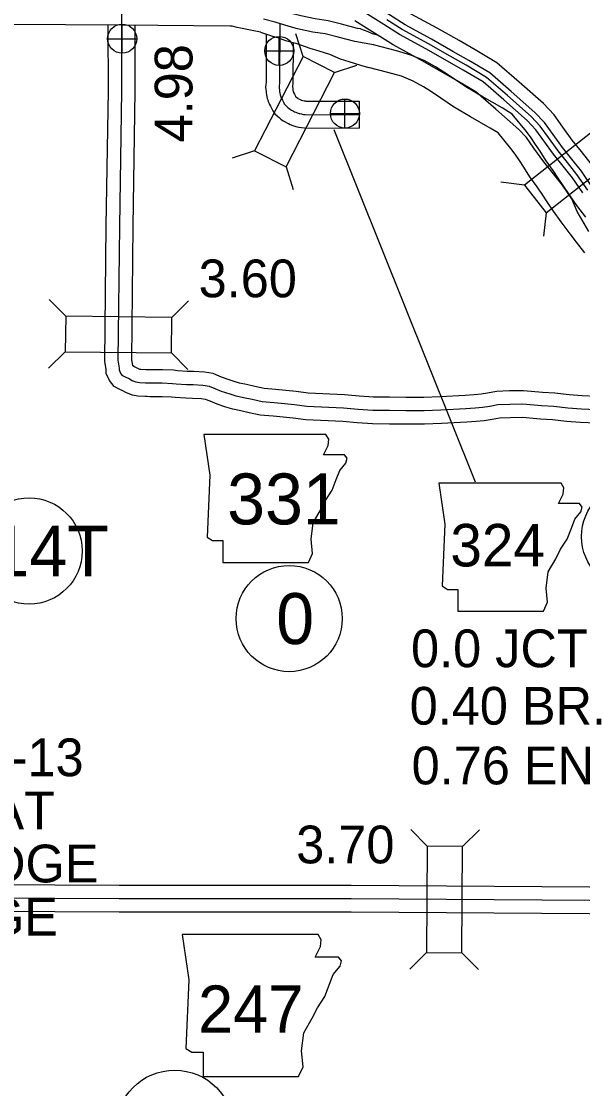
# Model space of a CAD drawing. Extents: x -83719 to 153526, y -11835 to 11446.
# Drawn here: x -1845 to -1635.6, y 787.2 to 1185.3 of the extents above; entities that cross this region are included whole.
import ezdxf

# ---------------------------------------------------------------- set-up
doc = ezdxf.new("R2010")
doc.units = 0
for name, color, linetype in [('Level 10', 7, 'Continuous'), ('Level 15', 7, 'Continuous'), ('Level 19', 7, 'Continuous'), ('Level 20', 7, 'Continuous'), ('Level 21', 7, 'Continuous'), ('Level 25', 7, 'Continuous'), ('Level 26', 7, 'Continuous'), ('Level 27', 7, 'Continuous'), ('Level 58', 7, 'Continuous'), ('Level 59', 7, 'Continuous')]:
    doc.layers.add(name, color=color, linetype=linetype)

msp = doc.modelspace()

# ---------------------------------------------------------------- linework, layer by layer
at = {"layer": 'Level 10'}
msp.add_line((-1718.97, 1155.5), (-1719, 1145.5), dxfattribs=at)
for points in [[(-1630.72, 1035.43), (-1636.35, 1035.7), (-1641.59, 1036.11), (-1646.79, 1036.67), (-1651.36, 1036.91), (-1658.04, 1037.54), (-1662.67, 1037.45), (-1666.61, 1037.3), (-1669.33, 1036.75), (-1672.31, 1036.31), (-1675.34, 1036.02), (-1678.85, 1035.83), (-1688.23, 1035.28), (-1694.65, 1035.02), (-1701.66, 1035.06), (-1707.72, 1035.12), (-1714.05, 1035.17), (-1719.75, 1035.54), (-1725.13, 1036.04), (-1738.94, 1036.66), (-1743.66, 1037.33), (-1747.36, 1037.73), (-1751.11, 1038.04), (-1755.88, 1038.48), (-1760.01, 1039.33), (-1763.15, 1040.05), (-1766.08, 1040.65), (-1768.69, 1041.45), (-1772.01, 1042.57), (-1774.61, 1043.59), (-1776.26, 1044.25), (-1777.89, 1044.54), (-1781.11, 1044.7), (-1783.67, 1044.74), (-1787.66, 1045.04), (-1788.97, 1045.18), (-1792.53, 1045.32), (-1795.07, 1045.32), (-1797.03, 1045.32), (-1798.05, 1045.35), (-1798.87, 1045.37), (-1801.58, 1045.45), (-1803.61, 1045.88), (-1805.82, 1046.73), (-1807.41, 1047.61), (-1808.26, 1048.03), (-1810.34, 1049.16), (-1812.16, 1051.34), (-1813.32, 1054.02), (-1813.4, 1055.47), (-1813.86, 1058.53), (-1813.33, 1109), (-1812.55, 1159.35), (-1812.59, 1183.76)], [(-1630.49, 1045.43), (-1635.72, 1045.68), (-1640.67, 1046.07), (-1646, 1046.64), (-1650.63, 1046.89), (-1657.67, 1047.55), (-1662.95, 1047.44), (-1667.8, 1047.27), (-1671.06, 1046.61), (-1673.52, 1046.24), (-1676.08, 1045.99), (-1679.41, 1045.82), (-1688.72, 1045.26), (-1694.81, 1045.02), (-1701.58, 1045.06), (-1707.63, 1045.12), (-1713.68, 1045.17), (-1718.97, 1045.52), (-1724.45, 1046.02), (-1738.02, 1046.63), (-1742.43, 1047.25), (-1746.4, 1047.68), (-1750.24, 1048), (-1754.41, 1048.38), (-1757.88, 1049.1), (-1761.02, 1049.83), (-1763.62, 1050.36), (-1765.63, 1050.97), (-1768.59, 1051.97), (-1770.94, 1052.89), (-1773.5, 1053.91), (-1776.75, 1054.49), (-1780.78, 1054.7), (-1783.22, 1054.73), (-1786.75, 1055), (-1788.24, 1055.16), (-1792.34, 1055.32), (-1795.05, 1055.32), (-1796.9, 1055.32), (-1797.8, 1055.34), (-1798.58, 1055.36), (-1800.4, 1055.42), (-1800.77, 1055.5), (-1801.57, 1055.81), (-1802.8, 1056.49), (-1803.49, 1056.82), (-1803.85, 1059.23), (-1803.33, 1108.87), (-1802.55, 1159.28), (-1802.59, 1183.62)], [(-1753.64, 1180.44), (-1753.74, 1162.78), (-1753.9, 1160.75), (-1753.8, 1159.84), (-1753.69, 1159.13), (-1753.65, 1158.61), (-1753.57, 1157.85), (-1753.27, 1156.58), (-1753.1, 1156.07), (-1752.94, 1155.48), (-1752.59, 1154.64), (-1752.41, 1154.3), (-1752.08, 1153.65), (-1751.61, 1152.7), (-1751.41, 1152.4), (-1751.16, 1151.93), (-1750.39, 1150.88), (-1749.49, 1149.96), (-1748.87, 1149.42), (-1748.25, 1148.87), (-1747.35, 1148.24), (-1746.59, 1147.79), (-1745.75, 1147.37), (-1745.41, 1147.2), (-1744.71, 1146.81), (-1743.69, 1146.44), (-1742.65, 1146.12), (-1742.12, 1146.02), (-1741.55, 1145.89), (-1741.32, 1145.85), (-1740.54, 1145.66), (-1739.32, 1145.55), (-1719, 1145.5)], [(-1743.65, 1177.4), (-1743.75, 1162.37), (-1743.85, 1160.95), (-1743.75, 1160.22), (-1743.7, 1159.56), (-1743.64, 1159.3), (-1743.52, 1158.95), (-1743.48, 1158.81), (-1743.14, 1158.12), (-1742.92, 1157.69), (-1742.77, 1157.46), (-1742.71, 1157.33), (-1742.58, 1157.2), (-1742.24, 1156.9), (-1742.05, 1156.73), (-1741.93, 1156.65), (-1741.82, 1156.58), (-1741.24, 1156.29), (-1740.7, 1156.02), (-1740.59, 1155.96), (-1740.54, 1155.94), (-1740.17, 1155.82), (-1740.09, 1155.81), (-1739.52, 1155.69), (-1739.15, 1155.61), (-1738.92, 1155.56), (-1738.88, 1155.55), (-1718.97, 1155.5)], [(-1554.09, 862.03), (-1633.06, 862.42), (-1721.91, 862.99), (-1808.49, 863.05), (-1880.63, 863.38), (-1913.72, 864.2)], [(-1545.78, 851.99), (-1633.12, 852.42), (-1721.95, 852.99), (-1808.52, 853.05), (-1880.77, 853.38), (-1913.96, 854.2)]]:
    msp.add_lwpolyline(points, dxfattribs=at)
at = {"layer": 'Level 15'}
for points in [[(-1718.53, 1182.47), (-1719.57, 1182.65), (-1725.6, 1184.21), (-1730.6, 1185.56), (-1735.36, 1186.25), (-1740.79, 1187.41), (-1743.71, 1188.18), (-1748.92, 1189.82), (-1753.56, 1191.03), (-1762.47, 1192.81)], [(-1764.54, 1183.03), (-1766.41, 1183.49), (-1766.81, 1183.53), (-1767.17, 1183.57), (-1807.63, 1183.86), (-1828.56, 1183.99), (-1882.43, 1184.28), (-1898.14, 1184.5), (-1899.72, 1184.43), (-1901.7, 1184.13), (-1905.12, 1183.71), (-1919.5, 1183.49)], [(-1755.8, 1181.28), (-1764.54, 1183.03)], [(-1718.53, 1182.47), (-1717.13, 1182.05), (-1715.72, 1181.51), (-1714.11, 1180.84), (-1712.28, 1180.29)], [(-1755.8, 1181.28), (-1751.32, 1179.77), (-1749.44, 1179.23), (-1746.43, 1178.22), (-1742.67, 1177.22), (-1737.44, 1175.27), (-1734.02, 1174.34), (-1730.07, 1173.13), (-1726.05, 1171.39), (-1722.83, 1170.31), (-1718.47, 1168.91), (-1715.51, 1168.14)], [(-1634.81, 1098.95), (-1637.89, 1102.95), (-1640.22, 1106.08), (-1643.65, 1110.51), (-1646.44, 1114.52), (-1648.64, 1117.68), (-1650.72, 1120.83), (-1652.63, 1123.59), (-1655.31, 1127.34), (-1657.55, 1130.96), (-1659.19, 1133.36), (-1660.82, 1135.77), (-1662.41, 1137.88), (-1667.14, 1143.7), (-1670.06, 1145.53), (-1677.46, 1149.71), (-1683.76, 1153.47), (-1688.51, 1156.65), (-1691.94, 1158.97), (-1694.97, 1160.88), (-1698.82, 1162.99), (-1703.21, 1164.81), (-1708.26, 1166.21), (-1715.51, 1168.14)]]:
    msp.add_lwpolyline(points, dxfattribs=at)
at = {"layer": 'Level 19'}
for points in [[(-1632.38, 1132.16), (-1636.03, 1136.79), (-1639.46, 1141.04), (-1642.94, 1145.85), (-1646.26, 1150.49), (-1650.22, 1154.62), (-1659.27, 1162.62), (-1667.58, 1169.84), (-1675.72, 1174.68), (-1681.72, 1178.11), (-1689.82, 1182.71), (-1699.54, 1188.01), (-1705.16, 1191.56), (-1709.17, 1194.09), (-1713.89, 1197.04), (-1722.93, 1202.04), (-1726.91, 1204.48), (-1730.37, 1206.52), (-1734.34, 1209), (-1741.18, 1213.94), (-1743.2, 1215.48), (-1745.83, 1217.57), (-1747.47, 1218.92)], [(-1631.88, 1123.31), (-1636.08, 1129.44), (-1639.61, 1133.93), (-1643.1, 1138.26), (-1646.66, 1143.17), (-1649.79, 1147.55), (-1653.4, 1151.32), (-1662.29, 1159.18), (-1670.28, 1166.11), (-1678.03, 1170.72), (-1683.98, 1174.13), (-1692.05, 1178.71), (-1701.86, 1184.06), (-1707.61, 1187.69), (-1711.6, 1190.21), (-1716.22, 1193.09), (-1725.24, 1198.08), (-1729.28, 1200.55), (-1732.75, 1202.6), (-1736.9, 1205.2), (-1743.91, 1210.25), (-1746.02, 1211.87), (-1748.72, 1214.01), (-1750.41, 1215.4)], [(-1635.56, 1121.32), (-1639.44, 1126.97), (-1642.87, 1131.33), (-1646.42, 1135.73), (-1650.04, 1140.74), (-1653.01, 1144.89), (-1656.29, 1148.31), (-1665.03, 1156.04), (-1672.73, 1162.72), (-1680.13, 1167.12), (-1686.05, 1170.51), (-1694.07, 1175.06), (-1703.97, 1180.47), (-1709.83, 1184.16), (-1713.82, 1186.68), (-1718.33, 1189.49), (-1727.34, 1194.48), (-1731.42, 1196.98), (-1734.92, 1199.04), (-1739.23, 1201.74), (-1746.39, 1206.91), (-1748.58, 1208.58), (-1751.33, 1210.77), (-1753.09, 1212.21)], [(-1633.27, 1106.98), (-1637.68, 1114.45), (-1639.61, 1119.12), (-1643.13, 1124.26), (-1646.46, 1128.48), (-1650.06, 1132.94), (-1653.76, 1138.06), (-1656.55, 1141.95), (-1659.47, 1145), (-1668.05, 1152.59), (-1675.42, 1158.99), (-1682.44, 1163.16), (-1688.32, 1166.53), (-1696.3, 1171.06), (-1706.29, 1176.51), (-1712.28, 1180.29), (-1716.25, 1182.8), (-1720.65, 1185.54)]]:
    msp.add_lwpolyline(points, dxfattribs=at)
at = {"layer": 'Level 20'}
for p, q in [((-1739.93, 1172.26), (-1742.63, 1180.63)), ((-1728.19, 1166.23), (-1719.81, 1168.93)), ((-1758.01, 1137.02), (-1766.39, 1134.33)), ((-1746.26, 1131), (-1743.57, 1122.62)), ((-1657.35, 1124.27), (-1666.08, 1125.31)), ((-1649.18, 1113.9), (-1650.22, 1105.16)), ((-1828.48, 1075.3), (-1834.64, 1081.59)), ((-1788.88, 1074.89), (-1782.6, 1081.05)), ((-1828.62, 1062.1), (-1834.91, 1055.94)), ((-1789.02, 1061.69), (-1782.86, 1055.4)), ((-1693.57, 877.61), (-1699.76, 883.87)), ((-1680.37, 877.52), (-1674.11, 883.7)), ((-1693.83, 838.01), (-1700.09, 831.82)), ((-1680.63, 837.92), (-1674.45, 831.66))]:
    msp.add_line(p, q, dxfattribs=at)
for points in [[(-1746.26, 1131), (-1728.19, 1166.23), (-1739.93, 1172.26), (-1758.01, 1137.02)], [(-1626.23, 1148.76), (-1657.35, 1124.27), (-1649.18, 1113.9), (-1618.06, 1138.39)], [(-1788.88, 1074.89), (-1828.48, 1075.3), (-1828.62, 1062.1), (-1789.02, 1061.69)], [(-1693.57, 877.61), (-1693.83, 838.01), (-1680.63, 837.92), (-1680.37, 877.52)]]:
    msp.add_lwpolyline(points, close=True, dxfattribs=at)
at = {"layer": 'Level 21'}
msp.add_lwpolyline([(-1728.45, 1144.99), (-1675.68, 1013.58)], dxfattribs=at)
for points in [[(-1777, 1031.21), (-1774.72, 1015.99), (-1775.73, 992.89), (-1773.7, 991.62), (-1769.9, 991.62), (-1769.9, 983.5), (-1737.92, 983.5), (-1736.4, 986.8), (-1736.91, 992.13), (-1736.15, 998.22), (-1733.36, 1003.04), (-1731.58, 1006.6), (-1729.04, 1010.4), (-1727.52, 1014.46), (-1726.25, 1017.76), (-1723.97, 1020.55), (-1723.46, 1022.33), (-1724.47, 1023.6), (-1732.34, 1023.6), (-1730.56, 1027.15), (-1730.31, 1029.44), (-1731.36, 1031.19)], [(-1689.29, 1013.03), (-1687.01, 997.81), (-1688.02, 974.71), (-1685.99, 973.44), (-1682.19, 973.44), (-1682.19, 965.32), (-1650.21, 965.32), (-1648.69, 968.62), (-1649.2, 973.95), (-1648.44, 980.04), (-1645.64, 984.86), (-1643.87, 988.42), (-1641.33, 992.22), (-1639.81, 996.28), (-1638.54, 999.58), (-1636.26, 1002.37), (-1635.75, 1004.15), (-1636.76, 1005.42), (-1644.63, 1005.42), (-1642.85, 1008.97), (-1642.6, 1011.26), (-1643.65, 1013.01)], [(-1785.05, 844.76), (-1782.51, 827.84), (-1783.64, 802.18), (-1781.38, 800.77), (-1777.15, 800.77), (-1777.15, 791.75), (-1741.63, 791.75), (-1739.93, 795.42), (-1740.5, 801.34), (-1739.65, 808.1), (-1736.55, 813.46), (-1734.58, 817.41), (-1731.76, 821.64), (-1730.07, 826.15), (-1728.66, 829.82), (-1726.12, 832.92), (-1725.55, 834.89), (-1726.68, 836.3), (-1735.42, 836.3), (-1733.45, 840.25), (-1733.17, 842.79), (-1734.34, 844.73)]]:
    msp.add_lwpolyline(points, close=True, dxfattribs=at)
at = {"layer": 'Level 26'}
for p, q in [((-1807.41, 1173.43), (-1807.41, 1184.26)), ((-1812.83, 1178.84), (-1802, 1178.84)), ((-1748.8, 1168.87), (-1748.8, 1179.7)), ((-1754.21, 1174.29), (-1743.38, 1174.29)), ((-1724.29, 1145.51), (-1724.29, 1156.34)), ((-1729.7, 1150.92), (-1718.87, 1150.92))]:
    msp.add_line(p, q, dxfattribs=at)
for centre in [(-1807.41, 1178.84), (-1748.8, 1174.29), (-1724.29, 1150.92)]:
    msp.add_circle(centre, 5.42, dxfattribs=at)
at = {"layer": 'Level 27'}
for centre, radius in [((-1616.21, 993.13), 19.8), ((-1842.12, 987.76), 19.8), ((-1745.1, 962.54), 19.8), ((-1787.8, 772.1), 22)]:
    msp.add_circle(centre, radius, dxfattribs=at)
at = {"layer": 'Level 59'}
for points in [[(-1630.61, 1040.43), (-1636.03, 1040.69), (-1641.13, 1041.09), (-1646.4, 1041.66), (-1650.99, 1041.9), (-1657.86, 1042.54), (-1662.81, 1042.44), (-1667.2, 1042.29), (-1670.19, 1041.68), (-1672.91, 1041.28), (-1675.71, 1041.01), (-1679.13, 1040.83), (-1688.48, 1040.27), (-1694.73, 1040.02), (-1701.62, 1040.06), (-1707.68, 1040.12), (-1713.87, 1040.17), (-1719.36, 1040.53), (-1724.79, 1041.03), (-1738.48, 1041.65), (-1743.05, 1042.29), (-1746.88, 1042.7), (-1750.68, 1043.02), (-1755.14, 1043.43), (-1758.95, 1044.21), (-1762.08, 1044.94), (-1764.85, 1045.51), (-1767.16, 1046.21), (-1770.3, 1047.27), (-1772.77, 1048.24), (-1774.88, 1049.08), (-1777.32, 1049.51), (-1780.95, 1049.7), (-1783.44, 1049.73), (-1787.21, 1050.02), (-1788.61, 1050.17), (-1792.44, 1050.32), (-1795.06, 1050.32), (-1796.96, 1050.32), (-1797.93, 1050.34), (-1798.73, 1050.37), (-1800.99, 1050.44), (-1802.19, 1050.69), (-1803.7, 1051.27), (-1805.1, 1052.05), (-1805.97, 1052.47), (-1807.11, 1053.09), (-1807.86, 1053.99), (-1808.37, 1055.18), (-1808.42, 1055.98), (-1808.85, 1058.88), (-1808.33, 1108.93), (-1807.55, 1159.32), (-1807.59, 1188.86)], [(-1634.36, 1112.33), (-1637.74, 1116.69), (-1640.46, 1120.59), (-1642.63, 1123.7), (-1644.7, 1126.85), (-1646.66, 1129.69), (-1649.27, 1133.33), (-1651.48, 1136.9), (-1653.18, 1139.39), (-1654.87, 1141.9), (-1656.6, 1144.18), (-1661.91, 1150.72), (-1665.63, 1153.04), (-1673.07, 1157.25), (-1679.21, 1160.91), (-1683.84, 1164.02), (-1687.34, 1166.38), (-1690.56, 1168.41), (-1694.78, 1170.72), (-1699.7, 1172.76), (-1705.07, 1174.26), (-1713.69, 1176.55), (-1720.63, 1177.76), (-1726.87, 1179.38), (-1731.61, 1180.65), (-1736.25, 1181.32), (-1741.95, 1182.55), (-1745.09, 1183.38), (-1750.31, 1185.01), (-1754.68, 1186.15)], [(-1748.61, 1184.5), (-1748.74, 1162.58), (-1748.88, 1160.84), (-1748.84, 1160.47), (-1748.72, 1159.67), (-1748.67, 1159.07), (-1748.63, 1158.71), (-1748.45, 1157.94), (-1748.31, 1157.51), (-1748.2, 1157.11), (-1748.06, 1156.78), (-1747.96, 1156.58), (-1747.61, 1155.89), (-1747.26, 1155.19), (-1747.09, 1154.93), (-1746.92, 1154.6), (-1746.58, 1154.14), (-1746.03, 1153.58), (-1745.56, 1153.16), (-1745.15, 1152.8), (-1744.64, 1152.44), (-1744.2, 1152.18), (-1743.49, 1151.83), (-1743.06, 1151.61), (-1742.65, 1151.38), (-1742.11, 1151.19), (-1741.41, 1150.97), (-1741.11, 1150.91), (-1740.54, 1150.79), (-1740.24, 1150.73), (-1739.73, 1150.61), (-1739.1, 1150.55), (-1718.99, 1150.5)], [(-1633.72, 1122.32), (-1637.76, 1128.21), (-1641.24, 1132.63), (-1644.76, 1136.99), (-1648.35, 1141.95), (-1651.4, 1146.22), (-1654.84, 1149.81), (-1663.66, 1157.61), (-1671.5, 1164.42), (-1679.08, 1168.92), (-1685.02, 1172.32), (-1693.06, 1176.89), (-1702.91, 1182.26), (-1708.72, 1185.93)], [(-1549.94, 857.01), (-1633.09, 857.42), (-1721.93, 857.99), (-1808.51, 858.05), (-1880.7, 858.38), (-1913.84, 859.2)]]:
    msp.add_lwpolyline(points, dxfattribs=at)

# ---------------------------------------------------------------- texts
at = {"layer": 'Level 21'}
for s, height, p in [('331', 19.008, (-1768.24, 997.68)), ('324', 15.84, (-1684.98, 982.01)), ('247', 17.6, (-1779.08, 808.1))]:
    msp.add_text(s, height=height, dxfattribs=at).set_placement(p)
at = {"layer": 'Level 25'}
msp.add_text('4.98', height=14.08, rotation=90, dxfattribs=at).set_placement((-1781.19, 1140.16))
for s, p in [('0.0 JCT. 64', (-1699.63, 944.41)), ('S.H. 7, S-13', (-1924.34, 903.76)), ('0.76 END', (-1699.4, 900.71)), ('ENDS AT', (-1914.1, 883.95)), ('TRAIL EDGE', (-1928.23, 864.15)), ('BRIDGE', (-1903.55, 844.34))]:
    msp.add_text(s, height=14.08, dxfattribs=at).set_placement(p)
at = {"layer": 'Level 27'}
for s, height, p in [('14T', 19.008, (-1856.18, 978.25)), ('0', 19.01, (-1749.94, 953.04))]:
    msp.add_text(s, height=height, dxfattribs=at).set_placement(p)
at = {"layer": 'Level 58'}
for s, p in [('3.60', (-1778.87, 1082.4)), ('0.40 BR.', (-1700.13, 922.99)), ('3.70', (-1742.47, 871.25))]:
    msp.add_text(s, height=14.08, dxfattribs=at).set_placement(p)

doc.saveas('drawing.dxf')
